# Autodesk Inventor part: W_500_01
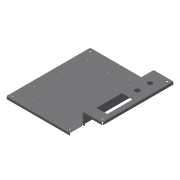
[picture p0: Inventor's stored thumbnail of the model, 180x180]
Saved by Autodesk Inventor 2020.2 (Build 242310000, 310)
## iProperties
Created: 2015-10
Part Number: W_500_01
Material: Stal
Document SubType Name: Konstrukcja blachowa
Designer: F.Stasiak
Density: 7.85 g/cm^3
Sheet Metal Rule: Blacha stalowa 1.5 mm/Kwadrat
Appearance: Stal
Description: Płyta montażowa
Catalog Web Link: www.expertbooks.pl
Manager: www.cadconsulting.pl
Company: Fabian Stasiak CAD Consulting
Author: F.Stasiak
Subject: Zbiór ćwiczeń. Autodesk Inventor 2020. Kurs Professional
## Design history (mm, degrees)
node "Powierzchnia1"
  sketch "Szkic1"
    geometry: L1 (-125, 165)-(125, 165); L2 (125, 165)-(125, -165); L3 (125, -165)-(-125, -165); L4 (-125, -165)-(-125, 165); L5 (-125, 165)-(125, -165); L6 (125, 165)-(-125, -165); 1 further point
    constraints: 12 end point, 2 midpoint, 2 parallel, 1 horizontal, 1 perpendicular
    dimensions: "d0" = 250 distance of L2.end L3.end; "d1" = 330 distance of L1.end L2.end
sketch "Szkic2"
  geometry: L1 (-125, 165)-(125, 165) reference; L2 (-125, -165)-(-125, 165) reference; L3 (-85, 115)-(75, 115); 4 further points
  constraints: 2 coincident, 2 end point, 1 horizontal, 1 midpoint
  dimensions: "d4" = 80 distance of point (-5, 115) L3.end; "d5" = 40 distance from line of L2 point (-85, 115); "d6" = 50 distance between parallel lines of L1 L3
hole "Otwór1" sketch "Szkic2" at (-85, 115), (-5, 115), (75, 115) diameter "d7" = 4.5; stored, may be unused: countersink angle "d11" = 90 deg, drill point angle "d13" = 118 deg; dims "d8" = 6, "d9" = 4, "d10" = 2, "d12" = 1.5 (= Grubość)
pattern_linear "Szyk prostokątny1" dims "d16" = 120
node "Kołnierz1"
node "Kołnierz2"
node "Kołnierz3"
sketch "Szkic6"
  geometry: L1 (72.696, 274)-(0, 274) reference; C1 r 9 at (36.348, 224); C2 r 9 at (36.348, 174); 2 further points
  constraints: 2 centre point, 2 vertical alignment, 1 midpoint
  dimensions: "d49" = 18 diameter of C1; "d50" = 50 distance from line of L1 C1.centre; "d81" = 18 diameter of C2; "d82" = 50 distance of C1.centre C2.centre
feature "Wytnij1" sketch "Szkic6" dims "d51" = 1.5 (= Grubość), "d52" = 0
sketch "Szkic7"
  geometry: L1 (-120.696, -162)-(125, -162) reference; L2 (-56.348, -127)-(60.652, -127); 3 further points
  constraints: 2 end point, 2 midpoint, 1 horizontal, 1 vertical alignment
  dimensions: "d53" = 117 distance of L2.start L2.end; "d54" = 35 distance between parallel lines of L2 L1
hole "Otwór2" sketch "Szkic7" at (-56.348, -127), (60.652, -127) diameter "d55" = 4.5; stored, may be unused: countersink angle "d59" = 90 deg, drill point angle "d61" = 118 deg; dims "d56" = 6, "d57" = 4, "d58" = 2, "d60" = 1.5 (= Grubość)
sketch "Szkic8"
  geometry: L1 (122, 162)-(-120.696, 162) reference; L2 (-122, 160.696)-(-122, -160.696) reference; L3 (112, -152)-(-112, -152); L4 (-112, -152)-(-112, 152); L5 (-112, 152)-(112, 152); L6 (112, 152)-(112, -152); L7 (112, -152)-(-112, 152); L8 (-112, -152)-(112, 152); 1 further point
  constraints: 12 end point, 2 midpoint, 2 parallel, 1 horizontal, 1 perpendicular
  dimensions: "d62" = 10 distance between parallel lines of L4 L2; "d63" = 10 distance between parallel lines of L1 L5 (= d62)
hole "Otwór3" sketch "Szkic8" at (-112, 152), (112, 152), (-112, -152), (112, -152) diameter "d64" = 6.5; stored, may be unused: countersink angle "d68" = 90 deg, drill point angle "d70" = 118 deg; dims "d65" = 6, "d66" = 4, "d67" = 2, "d69" = 1.5 (= Grubość)
sketch "Szkic9"
  geometry: L1 (0, 0)-(72.696, 0) reference; L2 (74, 1.304)-(74, 272.696) reference; L3 (72.696, 274)-(0, 274) reference; 3 further points
  constraints: 1 vertical alignment
  dimensions: "d71" = 10 distance from line of point (64, 10) L1; "d72" = 10 distance from line of point (64, 10) L2 (= d71); "d73" = 10 distance from line of L3 point (64, 264) (= d71)
hole "Otwór4" sketch "Szkic9" at (64, 264), (64, 10) diameter "d74" = 6.5; stored, may be unused: countersink angle "d78" = 90 deg, drill point angle "d80" = 118 deg; dims "d75" = 6, "d76" = 4, "d77" = 2, "d79" = 1.5 (= Grubość)
sketch "Szkic10"
  geometry: L1 (0, 0)-(72.696, 0) reference; L2 (15.348, 35)-(57.348, 35); L3 (57.348, 35)-(57.348, 135); L4 (57.348, 135)-(15.348, 135); L5 (15.348, 135)-(15.348, 35); C1 r 9 at (36.348, 174) reference; 2 further points
  constraints: 8 end point, 2 parallel, 1 horizontal, 1 midpoint, 1 perpendicular, 1 vertical alignment
  dimensions: "d83" = 42 distance of L4.end L3.end; "d84" = 100 distance of L3.end L2.end; "d85" = 35 distance between parallel lines of L1 L2
feature "Wytnij2" sketch "Szkic10" dims "d86" = 1.5 (= Grubość), "d87" = 0
node "Bryła1"
feature "Płyta1" dims "d88" = 1.5 (= Grubość)
sketch "Szkic3"
  geometry: L1 (0, 50)-(-280, 50); L2 (-280, 50)-(-280, 0); 1 other entity
  constraints: 4 end point, 4 other
feature "Płyta2" dims "d17" = 1.5 (= SzerokośćGięciaPodcięcia), "d18" = 0.75 (= GłębokośćGięciaPodcięcia), "d19" = 3 (= MinimalnaPozostałość), "d20" = 1.5 (= PromieńGięcia), "d21" = 50, "d22" = 90 deg, "d23" = 1.5 (= PromieńGięcia), "d24" = 6 (= RozmiarPodcięciaNarożnika), "d25" = 1.5 (= Wielk_odstępu), "d26" = 1.5 (= Rozmiar_promienia_Jacobiego), "d47" = 0, "d48" = 50, "d88" = 1.5 (= Grubość), "OdstępPołączenia" = 0.01
feature "Gięcie1" dims "d17" = 1.5 (= SzerokośćGięciaPodcięcia), "d18" = 0.75 (= GłębokośćGięciaPodcięcia), "d19" = 3 (= MinimalnaPozostałość), "d20" = 1.5 (= PromieńGięcia), "d21" = 50, "d22" = 90 deg, "d23" = 1.5 (= PromieńGięcia), "d88" = 1.5 (= Grubość), "OdstępPołączenia" = 0.01
feature "Narożnik1" dims "d21" = 50, "d22" = 90 deg, "d24" = 6 (= RozmiarPodcięciaNarożnika), "d25" = 1.5 (= Wielk_odstępu), "d26" = 1.5 (= Rozmiar_promienia_Jacobiego)
sketch "Szkic4"
  geometry: L1 (80, 0)-(80, 280); L2 (80, 280)-(0, 280); 1 other entity
  constraints: 4 end point, 4 other
feature "Płyta3" dims "d27" = 1.5 (= SzerokośćGięciaPodcięcia), "d28" = 0.75 (= GłębokośćGięciaPodcięcia), "d29" = 3 (= MinimalnaPozostałość), "d30" = 1.5 (= PromieńGięcia), "d31" = 80, "d32" = 90 deg, "d33" = 1.5 (= PromieńGięcia), "d34" = 6 (= RozmiarPodcięciaNarożnika), "d35" = 1.5 (= Wielk_odstępu), "d36" = 1.5 (= Rozmiar_promienia_Jacobiego), "d88" = 1.5 (= Grubość), "OdstępPołączenia" = 0.01
feature "Gięcie2" dims "d27" = 1.5 (= SzerokośćGięciaPodcięcia), "d28" = 0.75 (= GłębokośćGięciaPodcięcia), "d29" = 3 (= MinimalnaPozostałość), "d30" = 1.5 (= PromieńGięcia), "d31" = 80, "d32" = 90 deg, "d33" = 1.5 (= PromieńGięcia), "d88" = 1.5 (= Grubość), "OdstępPołączenia" = 0.01
feature "Narożnik2" dims "d31" = 80, "d32" = 90 deg, "d34" = 6 (= RozmiarPodcięciaNarożnika), "d35" = 1.5 (= Wielk_odstępu), "d36" = 1.5 (= Rozmiar_promienia_Jacobiego)
sketch "Szkic5"
  geometry: L1 (0, -10)-(247, -10); L2 (247, -10)-(247, 0); 1 other entity
  constraints: 4 end point, 4 other
feature "Płyta4" dims "d37" = 1.5 (= SzerokośćGięciaPodcięcia), "d38" = 0.75 (= GłębokośćGięciaPodcięcia), "d39" = 3 (= MinimalnaPozostałość), "d40" = 1.5 (= PromieńGięcia), "d41" = 10, "d42" = 90 deg, "d43" = 1.5 (= PromieńGięcia), "d44" = 6 (= RozmiarPodcięciaNarożnika), "d45" = 1.5 (= Wielk_odstępu), "d46" = 1.5 (= Rozmiar_promienia_Jacobiego), "d88" = 1.5 (= Grubość), "OdstępPołączenia" = 0.01
feature "Gięcie3" dims "d37" = 1.5 (= SzerokośćGięciaPodcięcia), "d38" = 0.75 (= GłębokośćGięciaPodcięcia), "d39" = 3 (= MinimalnaPozostałość), "d40" = 1.5 (= PromieńGięcia), "d41" = 10, "d42" = 90 deg, "d43" = 1.5 (= PromieńGięcia), "d88" = 1.5 (= Grubość), "OdstępPołączenia" = 0.01
feature "Narożnik3" dims "d41" = 10, "d42" = 90 deg, "d44" = 6 (= RozmiarPodcięciaNarożnika), "d45" = 1.5 (= Wielk_odstępu), "d46" = 1.5 (= Rozmiar_promienia_Jacobiego)
other parameters: "Grubość" = 1.5 (derived), "WspółczynnikK" = 4.4, "PromieńGięcia" = 1.5 (= Grubość), "SzerokośćGięciaPodcięcia" = 1.5 (= Grubość), "GłębokośćGięciaPodcięcia" = 0.75 (= 0.5 x Grubość), "RozmiarPodcięciaNarożnika" = 6 (= 4 x Grubość), "MinimalnaPozostałość" = 3 (= 2 x Grubość), "PromieńPrzejścia" = 1.5 (= PromieńGięcia), "Rozmiar_promienia_Jacobiego" = 1.5 (= PromieńGięcia), "Wielk_odstępu" = 1.5 (= Grubość), "d2" = 1.5 (= PromieńGięcia)
